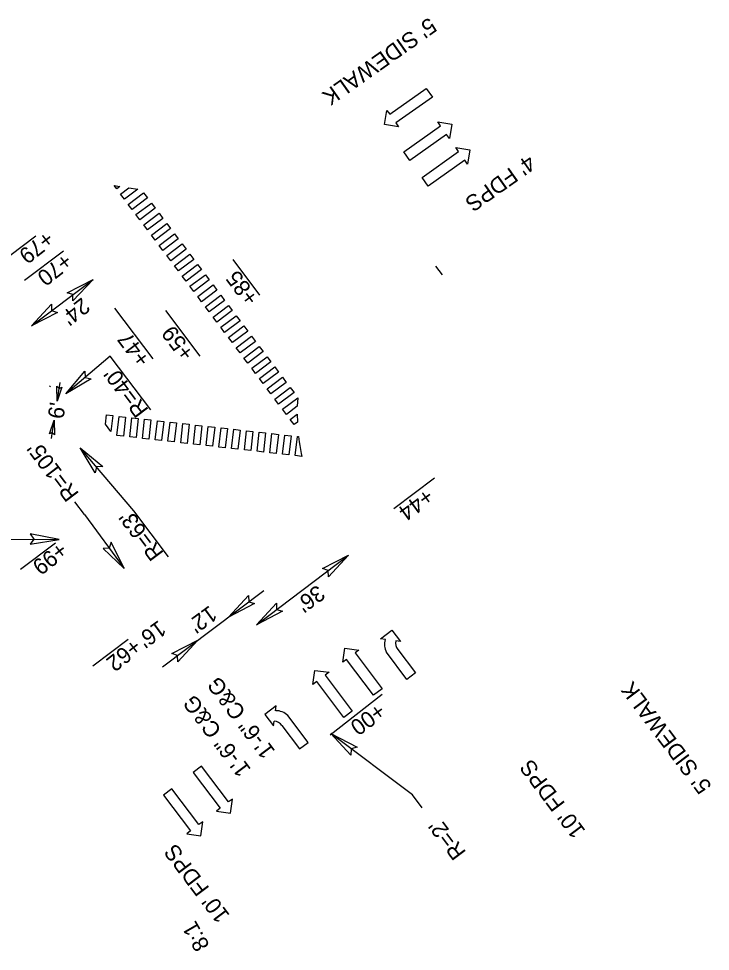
# Model space of a CAD drawing. Extents: x 1262692 to 1264138, y 775643 to 777474.
# Drawn here: x 1263379.2 to 1263595, y 776393.9 to 776684.7 of the extents above; entities that cross this region are included whole.
import ezdxf

# ---------------------------------------------------------------- set-up
doc = ezdxf.new("R2010")
doc.units = 0
for name, color, linetype in [('Prop Dimension', 7, 'Continuous'), ('Prop Dimension Text', 7, 'Continuous'), ('Prop Lane Arrow CELL', 7, 'Continuous'), ('Prop Mkg Solid White Crosswalks', 7, 'Continuous'), ('Prop Terminator CELL', 7, 'Continuous')]:
    doc.layers.add(name, color=color, linetype=linetype)

msp = doc.modelspace()

# ---------------------------------------------------------------- linework, layer by layer
at = {"layer": 'Prop Dimension'}
for p, q in [((1263368.14, 776604.63), (1263384.56, 776617)), ((1263381.01, 776603.12), (1263393.17, 776612.27)), ((1263383.15, 776588.91), (1263402.37, 776603.38)), ((1263391.18, 776565.46), (1263392.08, 776571.21)), ((1263389.36, 776553.79), (1263390.25, 776559.52)), ((1263496.22, 776531.92), (1263508.98, 776541.52)), ((1263453.34, 776495.71), (1263482.1, 776517.37)), ((1263424, 776482.54), (1263455.63, 776506.37))]:
    msp.add_line(p, q, dxfattribs=at)
at = {"layer": 'Prop Dimension Text'}
for p, q in [((1263445.98, 776609.58), (1263454.36, 776598.44)), ((1263509.24, 776607.56), (1263511.32, 776604.77)), ((1263409.1, 776594.46), (1263421.04, 776578.61)), ((1263424.95, 776593.74), (1263435.73, 776579.42)), ((1263420.37, 776562.7), (1263407.76, 776579.45)), ((1263388.95, 776570.15), (1263388.82, 776569.85)), ((1263415.12, 776531.27), (1263398.35, 776550.9)), ((1263399.71, 776530.06), (1263396.7, 776534.05)), ((1263425.97, 776516.87), (1263415.12, 776531.27)), ((1263369.67, 776522.44), (1263391.79, 776522.29)), ((1263390.71, 776521.17), (1263379.69, 776512.88)), ((1263413.3, 776491.12), (1263402.28, 776482.83)), ((1263476.33, 776461.33), (1263492.58, 776474.07))]:
    msp.add_line(p, q, dxfattribs=at)
for points in [[(1263407.76, 776579.45), (1263393.92, 776567.72)], [(1263399.66, 776530.11), (1263412.14, 776513.2)], [(1263505.06, 776438.65), (1263502.05, 776442.65), (1263476.62, 776461.76)]]:
    msp.add_lwpolyline(points, dxfattribs=at)
at = {"layer": 'Prop Lane Arrow CELL'}
for p, q in [((1263494.95, 776654.87), (1263506.37, 776662.96)), ((1263506.37, 776662.96), (1263508.28, 776660.26)), ((1263508.28, 776660.26), (1263496.85, 776652.18)), ((1263493.36, 776651.66), (1263494.08, 776656.09)), ((1263494.08, 776656.09), (1263494.95, 776654.87)), ((1263510.79, 776651.26), (1263509.93, 776652.48)), ((1263509.93, 776652.48), (1263514.29, 776651.77)), ((1263497.72, 776650.95), (1263493.36, 776651.66)), ((1263496.85, 776652.18), (1263497.72, 776650.95)), ((1263499.37, 776643.17), (1263510.79, 776651.26)), ((1263514.29, 776651.77), (1263513.57, 776647.34)), ((1263512.7, 776648.57), (1263501.27, 776640.48)), ((1263513.57, 776647.34), (1263512.7, 776648.57)), ((1263516.47, 776643.24), (1263515.6, 776644.47)), ((1263515.6, 776644.47), (1263519.96, 776643.76)), ((1263519.96, 776643.76), (1263519.24, 776639.33)), ((1263501.27, 776640.48), (1263499.37, 776643.17)), ((1263505.04, 776635.16), (1263516.47, 776643.24)), ((1263518.37, 776640.55), (1263506.94, 776632.46)), ((1263519.24, 776639.33), (1263518.37, 776640.55)), ((1263506.94, 776632.46), (1263505.04, 776635.16)), ((1263492.12, 776491.32), (1263495.6, 776494.01)), ((1263495.6, 776494.01), (1263498.35, 776490.45)), ((1263493.59, 776491.12), (1263492.12, 776491.32)), ((1263498.35, 776490.45), (1263496.88, 776490.65)), ((1263480.32, 776484.01), (1263480.9, 776488.39)), ((1263480.9, 776488.39), (1263485.35, 776487.8)), ((1263485.35, 776487.8), (1263484.16, 776486.9)), ((1263484.16, 776486.9), (1263492.58, 776475.71)), ((1263500.34, 776478.67), (1263493.99, 776487.1)), ((1263497.47, 776487.97), (1263502.97, 776480.66)), ((1263481.52, 776484.91), (1263480.32, 776484.01)), ((1263489.94, 776473.73), (1263481.52, 776484.91)), ((1263470.97, 776477.07), (1263471.56, 776481.45)), ((1263471.56, 776481.45), (1263476.01, 776480.86)), ((1263476.01, 776480.86), (1263474.81, 776479.96)), ((1263472.17, 776477.97), (1263470.97, 776477.07)), ((1263480.6, 776466.79), (1263472.17, 776477.97)), ((1263474.81, 776479.96), (1263483.23, 776468.77)), ((1263502.97, 776480.66), (1263500.34, 776478.67)), ((1263492.58, 776475.71), (1263489.94, 776473.73)), ((1263459.57, 776470.36), (1263456.03, 776467.75)), ((1263459.36, 776468.89), (1263459.57, 776470.36)), ((1263456.03, 776467.75), (1263458.69, 776464.13)), ((1263469.46, 776458.97), (1263463.12, 776467.4)), ((1263483.23, 776468.77), (1263480.6, 776466.79)), ((1263458.69, 776464.13), (1263458.9, 776465.6)), ((1263461.32, 776464.3), (1263466.83, 776456.99)), ((1263466.83, 776456.99), (1263469.46, 776458.97)), ((1263436.26, 776451.63), (1263433.63, 776449.64)), ((1263433.63, 776449.64), (1263442.05, 776438.46)), ((1263444.69, 776440.44), (1263436.26, 776451.63)), ((1263427.01, 776444.56), (1263424.38, 776442.57)), ((1263435.44, 776433.38), (1263427.01, 776444.56)), ((1263424.38, 776442.57), (1263432.8, 776431.39)), ((1263445.88, 776441.35), (1263444.69, 776440.44)), ((1263445.22, 776436.91), (1263445.88, 776441.35)), ((1263442.05, 776438.46), (1263440.85, 776437.56)), ((1263440.85, 776437.56), (1263445.22, 776436.91)), ((1263436.63, 776434.28), (1263435.44, 776433.38)), ((1263435.97, 776429.84), (1263436.63, 776434.28)), ((1263432.8, 776431.39), (1263431.6, 776430.49)), ((1263431.6, 776430.49), (1263435.97, 776429.84))]:
    msp.add_line(p, q, dxfattribs=at)
for centre, radius, start, end in [((1263498.6, 776489.58), 5.25, 162.9996, 208.3113), ((1263500.06, 776489.93), 3.27, 167.3292, 216.9874), ((1263459.46, 776463.65), 5.25, 45.6635, 90.9752), ((1263458.72, 776462.34), 3.27, 36.9874, 86.6456)]:
    msp.add_arc(centre, radius, start, end, dxfattribs=at)
at = {"layer": 'Prop Mkg Solid White Crosswalks'}
for points in [[(1263410.78, 776632.35), (1263409.76, 776631.59), (1263408.93, 776632.7)], [(1263416.36, 776631.55), (1263412.17, 776628.39), (1263410.97, 776629.99), (1263413.52, 776631.91)], [(1263418.16, 776630.4), (1263419.37, 776628.81), (1263414.58, 776625.2), (1263413.37, 776626.79)], [(1263420.57, 776627.21), (1263421.77, 776625.61), (1263416.98, 776622), (1263415.78, 776623.6)], [(1263422.98, 776624.01), (1263424.18, 776622.42), (1263419.39, 776618.81), (1263418.19, 776620.4)], [(1263425.38, 776620.82), (1263426.59, 776619.22), (1263421.8, 776615.61), (1263420.59, 776617.21)], [(1263427.79, 776617.62), (1263428.99, 776616.03), (1263424.2, 776612.42), (1263423, 776614.01)], [(1263430.2, 776614.43), (1263431.4, 776612.83), (1263426.61, 776609.22), (1263425.41, 776610.82)], [(1263432.6, 776611.23), (1263433.81, 776609.64), (1263429.01, 776606.03), (1263427.81, 776607.62)], [(1263435.01, 776608.04), (1263436.21, 776606.44), (1263431.42, 776602.83), (1263430.22, 776604.43)], [(1263437.42, 776604.84), (1263438.62, 776603.25), (1263433.83, 776599.64), (1263432.62, 776601.23)], [(1263439.82, 776601.65), (1263441.03, 776600.05), (1263436.23, 776596.44), (1263435.03, 776598.04)], [(1263442.23, 776598.45), (1263443.43, 776596.85), (1263438.64, 776593.25), (1263437.44, 776594.84)], [(1263444.64, 776595.26), (1263445.84, 776593.66), (1263441.05, 776590.05), (1263439.84, 776591.65)], [(1263447.04, 776592.06), (1263448.25, 776590.46), (1263443.45, 776586.85), (1263442.25, 776588.45)], [(1263449.45, 776588.87), (1263450.65, 776587.27), (1263445.86, 776583.66), (1263444.66, 776585.26)], [(1263451.86, 776585.67), (1263453.06, 776584.07), (1263448.27, 776580.46), (1263447.06, 776582.06)], [(1263454.26, 776582.48), (1263455.47, 776580.88), (1263450.67, 776577.27), (1263449.47, 776578.87)], [(1263456.67, 776579.28), (1263457.87, 776577.68), (1263453.08, 776574.07), (1263451.88, 776575.67)], [(1263459.08, 776576.09), (1263460.28, 776574.49), (1263455.49, 776570.88), (1263454.28, 776572.48)], [(1263461.48, 776572.89), (1263462.69, 776571.29), (1263457.89, 776567.68), (1263456.69, 776569.28)], [(1263463.89, 776569.7), (1263465.09, 776568.1), (1263460.3, 776564.49), (1263459.1, 776566.09)], [(1263466.12, 776563.87), (1263462.7, 776561.29), (1263461.5, 776562.89), (1263466.24, 776566.46)], [(1263408.53, 776560.9), (1263407.97, 776555.95), (1263406.22, 776558.25), (1263406.54, 776561.13)], [(1263410.52, 776560.68), (1263412.5, 776560.45), (1263411.83, 776554.49), (1263409.84, 776554.72)], [(1263414.49, 776560.23), (1263416.48, 776560.01), (1263415.81, 776554.04), (1263413.82, 776554.27)], [(1263418.47, 776559.78), (1263420.45, 776559.56), (1263419.78, 776553.59), (1263417.79, 776553.82)], [(1263465.11, 776558.1), (1263463.91, 776559.7), (1263466.1, 776561.35), (1263466.17, 776558.89)], [(1263422.44, 776559.33), (1263424.43, 776559.11), (1263423.76, 776553.15), (1263421.77, 776553.37)], [(1263426.42, 776558.88), (1263428.4, 776558.66), (1263427.73, 776552.7), (1263425.74, 776552.92)], [(1263430.39, 776558.43), (1263432.38, 776558.21), (1263431.7, 776552.25), (1263429.72, 776552.47)], [(1263434.37, 776557.98), (1263436.35, 776557.76), (1263435.68, 776551.8), (1263433.69, 776552.02)], [(1263438.34, 776557.54), (1263440.33, 776557.31), (1263439.65, 776551.35), (1263437.67, 776551.57)], [(1263442.31, 776557.09), (1263444.3, 776556.86), (1263443.63, 776550.9), (1263441.64, 776551.12)], [(1263446.29, 776556.64), (1263448.28, 776556.41), (1263447.6, 776550.45), (1263445.62, 776550.67)], [(1263450.26, 776556.19), (1263452.25, 776555.96), (1263451.58, 776550), (1263449.59, 776550.23)], [(1263454.24, 776555.74), (1263456.23, 776555.51), (1263455.55, 776549.55), (1263453.57, 776549.78)], [(1263458.21, 776555.29), (1263460.2, 776555.06), (1263459.53, 776549.1), (1263457.54, 776549.33)], [(1263462.19, 776554.84), (1263464.18, 776554.62), (1263463.5, 776548.65), (1263461.51, 776548.88)], [(1263467.48, 776548.2), (1263465.49, 776548.43), (1263466.16, 776554.39), (1263466.52, 776554.35), (1263466.72, 776552.69), (1263466.88, 776551.57), (1263467.3, 776549.09)]]:
    msp.add_lwpolyline(points, close=True, dxfattribs=at)
at = {"layer": 'Prop Terminator CELL'}
for points in [[(1263394.25, 776599.21), (1263402.37, 776603.38), (1263396.11, 776596.66), (1263396.06, 776598.63)], [(1263391.27, 776593.08), (1263383.15, 776588.91), (1263389.42, 776595.63), (1263389.46, 776593.66)], [(1263401.79, 776572.36), (1263393.92, 776567.72), (1263399.79, 776574.8), (1263399.95, 776572.83)], [(1263392.64, 776569.78), (1263391.18, 776565.46), (1263391.09, 776570.05), (1263391.79, 776569.36)], [(1263388.79, 776555.19), (1263390.25, 776559.52), (1263390.35, 776554.92), (1263389.65, 776555.61)], [(1263403.02, 776543.05), (1263398.35, 776550.9), (1263405.44, 776545.06), (1263403.48, 776544.89)], [(1263382.77, 776520.87), (1263391.79, 776522.29), (1263382.76, 776524.02), (1263383.89, 776522.4)], [(1263405.55, 776519.52), (1263412.14, 776513.2), (1263408.05, 776521.43), (1263407.45, 776519.56)], [(1263473.98, 776513.2), (1263482.1, 776517.37), (1263475.83, 776510.65), (1263475.79, 776512.62)], [(1263452.78, 776502.28), (1263444.66, 776498.1), (1263450.93, 776504.82), (1263450.97, 776502.85)], [(1263461.46, 776499.89), (1263453.34, 776495.71), (1263459.61, 776502.44), (1263459.65, 776500.47)], [(1263426.97, 776486.72), (1263435.09, 776490.89), (1263428.83, 776484.17), (1263428.78, 776486.14)], [(1263482.83, 776455.06), (1263476.62, 776461.76), (1263484.78, 776457.53), (1263482.89, 776456.96)]]:
    msp.add_lwpolyline(points, close=True, dxfattribs=at)

# ---------------------------------------------------------------- texts
at = {"layer": 'Prop Dimension'}
msp.add_text("6'", height=5, rotation=81.4269, dxfattribs=at).set_placement((1263393.13, 776559.64))
at = {"layer": 'Prop Dimension Text'}
for s, rotation, p in [("5' SIDEWALK", 215.2883, (1263507.26, 776685.31)), ("4' FDPS", 215.2883, (1263538.2, 776642.51)), (' +79', 218.0143, (1263389.21, 776619.95)), (' +70', 218.0143, (1263394.91, 776613.06)), ('+85', 126.9874, (1263454.3, 776597.59)), (" 24'", 218.0143, (1263400.38, 776599.11)), ('+59', 126.9874, (1263434.23, 776580.4)), ('+47', 126.9874, (1263420.49, 776578.5)), ("R=40'", 126.9874, (1263419.9, 776562.72)), ("R=105'", 126.9874, (1263398.19, 776536.55)), ('+44', 216.1502, (1263506.35, 776538.51)), ("R=63'", 126.9874, (1263424.61, 776518.06)), (' +99', 218.0143, (1263393.41, 776522.94)), ("36'", 216.1502, (1263472.38, 776508.36)), ("12'", 216.1502, (1263438.74, 776501.91)), ("16'", 216.1502, (1263422.86, 776497.31)), (' +62', 218.0143, (1263416.48, 776492.82)), ('1\'-6" C&G', 126.9874, (1263459.41, 776456.3)), ("5' SIDEWALK", 126.9874, (1263595.66, 776445.36)), ('1\'-6" C&G', 126.9874, (1263451.85, 776450.61)), ('+00', 216.1502, (1263491.33, 776471.57)), ("10' FDPS", 126.9874, (1263556.23, 776431.47)), ("R=2'", 126.9874, (1263518.96, 776424.74)), ("10' FDPS", 126.9874, (1263445.24, 776405.09)), ('8:1', 119.8624, (1263438.9, 776395.68))]:
    msp.add_text(s, height=5, rotation=rotation, dxfattribs=at).set_placement(p)

doc.saveas('drawing.dxf')
